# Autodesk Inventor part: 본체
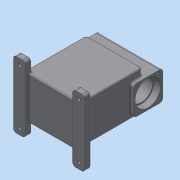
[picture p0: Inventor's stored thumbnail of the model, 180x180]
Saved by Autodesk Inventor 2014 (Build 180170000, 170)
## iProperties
Created: 2025-06
Part Number: 본체
Material: 일반
Document SubType Name: Modeling
Designer: dg
Density: 1 g/cm^3
Appearance: 기본값
Author: dg
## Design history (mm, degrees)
sketch "스케치1"
  geometry: L1 (-93, -103)-(93, -103); L2 (93, -103)-(93, 103); L3 (93, 103)-(-93, 103); L4 (-93, 103)-(-93, -103); L5 (-93, -103)-(93, 103); L6 (93, -103)-(-93, 103); 1 further point
  constraints: 12 end point, 2 midpoint, 2 parallel, 1 horizontal, 1 perpendicular
  dimensions: "d0" = 186 distance of L3.end L2.end; "d1" = 206 distance of L2.end L1.end
extrude "돌출1" new body sketch "스케치1" stored distance "d2" = 140; taper "d3" = 0 deg
sketch "스케치2"
  geometry: L1 (140, 206)-(0, 206) reference; L2 (140, 206)-(140, 0) reference; L3 (125, 206)-(125, 17); L4 (125, 17)-(140, 17); 1 further point
  constraints: 4 end point, 2 point on line, 1 parallel, 1 perpendicular
  dimensions: "d4" = 189 distance between parallel lines of L1 L4; "d5" = 15 distance of L3.end L4.end
extrude "돌출2" cut sketch "스케치2" stored distance "d6" = 140; taper "d7" = 0 deg
node "작업 평면2"
sketch "스케치6"
  geometry: L1 (-25, -180)-(211, -180); L2 (211, -180)-(211, 40); L3 (211, 40)-(-25, 40); L4 (-25, 40)-(-25, -180); L5 (-25, -180)-(211, 40); L6 (211, -180)-(-25, 40); 1 further point
  constraints: 12 end point, 2 midpoint, 2 parallel, 1 horizontal, 1 perpendicular
  dimensions: "d18" = 220 distance of L1.end L2.end; "d19" = 236 distance of L2.end L3.end
extrude "돌출4" join sketch "스케치6" distance "d20" = 20; taper "d21" = 0 deg
sketch "스케치7"
  geometry: L1 (236, 0)-(0, 0) reference; L2 (236, 0)-(236, 20) reference; L3 (0, 20)-(236, 20) reference; L4 (0, 0)-(0, 20) reference; L5 (40, 10)-(40, 0); L6 (196, 10)-(196, 0); L7 (40, 10)-(196, 10); 1 further point
  constraints: 6 end point, 4 perpendicular, 2 point on line, 1 parallel
  dimensions: "d22" = 40 distance between parallel lines of L4 L5; "d23" = 40 distance between parallel lines of L2 L6; "d127" = 10 distance between parallel lines of L1 L7
extrude "돌출5" cut sketch "스케치7" stored distance "d24" = 20; taper "d25" = 0 deg
node "작업 평면4"
sketch "스케치13"
  geometry: L1 (62, 48)-(158, 48); L2 (158, 48)-(158, -48); L3 (158, -48)-(62, -48); L4 (62, -48)-(62, 48); L5 (62, 48)-(158, -48); L6 (158, 48)-(62, -48); L7 (-113, -110)-(-113, 110) reference; L8 (-93, 70)-(103, 70) reference; L9 (-86, -55)-(103, -55) reference; L10 (-113, 110)-(-93, 110) reference; 5 further points
  constraints: 12 end point, 4 midpoint, 2 parallel, 1 horizontal, 1 horizontal alignment, 1 perpendicular
  dimensions: "d52" = 96 distance of L2.end L3.end; "d53" = 96 distance of L1.end L2.end; "d54" = 223 distance from line of L7 point (110, 0)
extrude "돌출6" join sketch "스케치13" distance "d56" = 210; taper "d57" = 0 deg
sketch "스케치14"
  geometry: L1 (48, 158)-(-48, 158) reference; L2 (-48, 158)-(-48, 62) reference; 4 further points
  constraints: 2 midpoint, 1 horizontal alignment, 1 vertical alignment
hole "구멍4" sketch "스케치14" at (0, 110) diameter "d58" = 85; stored, may be unused: countersink angle "d62" = 90 deg, drill point angle "d64" = 0 deg; dims "d59" = 6, "d60" = 62, "d61" = 16, "d63" = 23
fillet "모깎기1" dims "d72" = 1.1
chamfer "모따기1" distance "d73" = 1; stored, may be unused: second distance "d74" = 2, angle "d75" = 45 deg
fillet "모깎기2" dims "d76" = 10
sketch "스케치16"
  geometry: A1 r 10 centre (-38, 148) between (-38, 158) and (-48, 148) reference; 1 further point
hole "구멍6" sketch "스케치16" at (-38, 148) diameter "d77" = 4.917; stored, may be unused: countersink angle "d81" = 90 deg, drill point angle "d83" = 118 deg; dims "d78" = 12, "d79" = 62, "d80" = 16, "d82" = 14
sketch "스케치17"
  geometry: L1 (211, 180)-(-25, 180) reference; 4 further points
  constraints: 2 vertical alignment, 1 point on line
  dimensions: "d93" = 180 distance of point (191, 160) point (191, -20); "d94" = 90 vertical distance of point (93, 70) point (191, 160)
hole "구멍7" sketch "스케치17" at (191, 160), (191, -20) diameter "d95" = 11; stored, may be unused: countersink angle "d99" = 90 deg, drill point angle "d101" = 118 deg; dims "d96" = 16, "d97" = 28, "d98" = 2, "d100" = 18
sketch "스케치18"
  geometry: L1 (198, 55)-(-12, 55) reference; 2 further points
  constraints: 1 vertical alignment, 1 other
  dimensions: "d102" = 30 distance from line of point (93, 25) L1
feature "엠보싱1" sketch "스케치18" dims "d103" = 0.5, "d104" = 0
fillet "모깎기6" dims "d117" = 10
fillet "모깎기8" dims "d119" = 3
fillet "모깎기9" dims "d120" = 10
fillet "모깎기10" dims "d121" = 3
sketch "스케치22"
  geometry: L1 (0, 0)-(236, 0) reference; L2 (40, -10)-(196, -10) reference; L3 (40, -10)-(40, 0); L4 (196, -10)-(196, 0); 1 further point
  constraints: 4 end point, 2 perpendicular, 2 point on line
extrude "돌출8" cut sketch "스케치22" stored distance "d130" = 210; taper "d131" = 0 deg
sketch "스케치23"
  geometry: L1 (40, -10)-(196, -10) reference; L2 (0, 0)-(236, 0) reference; L3 (40, -20)-(0, -20) reference; L4 (40, -10)-(40, 0); L5 (196, -10)-(196, 0); 1 further point
  constraints: 4 end point, 2 perpendicular, 2 point on line
extrude "돌출9" cut sketch "스케치23" stored distance "d132" = 210; taper "d133" = 0 deg
fillet "모깎기16" dims "d134" = 10
fillet "모깎기17" dims "d135" = 3
fillet "모깎기18" dims "d136" = 3
fillet "모깎기19" dims "d137" = 3
fillet "모깎기20" dims "d138" = 3
sketch "스케치26"
  geometry: C1 r 41.4 at (0, 0) reference; 1 further point
hole "구멍9" sketch "스케치26" at (0, 0) diameter "d142" = 77; stored, may be unused: countersink angle "d146" = 90 deg, drill point angle "d148" = 0 deg; dims "d143" = 16, "d144" = 28, "d145" = 2, "d147" = 18
sketch "스케치28"
  geometry: L1 (5, -27)-(-15, -27) reference; 2 further points
  constraints: 1 vertical alignment
  dimensions: "d161" = 123 distance from line of L1 point (93, 96)
hole "구멍11" sketch "스케치28" at (93, 96) diameter "d162" = 172; stored, may be unused: countersink angle "d166" = 90 deg, drill point angle "d168" = 0 deg; dims "d163" = 16, "d164" = 28, "d165" = 2, "d167" = 102
sketch "스케치29"
  geometry: C1 r 86 at (0, 0) reference; 1 further point
hole "구멍12" sketch "스케치29" at (0, 0) diameter "d169" = 62; stored, may be unused: countersink angle "d173" = 90 deg, drill point angle "d175" = 0 deg; dims "d170" = 16, "d171" = 28, "d172" = 2, "d174" = 16
sketch "스케치30"
  geometry: C1 r 31 at (0, 0) reference; 1 further point
hole "구멍13" sketch "스케치30" at (0, 0) diameter "d176" = 54; stored, may be unused: countersink angle "d180" = 90 deg, drill point angle "d182" = 0 deg; dims "d177" = 16, "d178" = 28, "d179" = 2, "d181" = 3
chamfer "모따기3" distance "d183" = 1; stored, may be unused: second distance "d184" = 2, angle "d185" = 45 deg
chamfer "모따기4" distance "d186" = 1; stored, may be unused: second distance "d187" = 2, angle "d188" = 45 deg
fillet "모깎기21" dims "d189" = 1
fillet "모깎기22" dims "d190" = 3
sketch "스케치31"
  geometry: C1 r 87 at (93, 96) reference; 2 further points
  dimensions: "d191" = 75 horizontal distance of C1.centre point (18, 171); "d192" = 75 horizontal distance of C1.centre point (18, 171)
hole "구멍14" sketch "스케치31" at (18, 171) diameter "d193" = 6.647; stored, may be unused: countersink angle "d197" = 90 deg, drill point angle "d199" = 118 deg; dims "d194" = 16, "d195" = 28, "d196" = 2, "d198" = 18
node "솔리드1"
mirror "대칭1"
mirror "대칭2"
mirror "대칭3"
pattern_circular "원형 패턴4" dims angle "d201" = 360 deg
pattern_circular "원형 패턴5" dims angle "d204" = 360 deg
mirror "대칭4"
other parameters: "d51" = 105
